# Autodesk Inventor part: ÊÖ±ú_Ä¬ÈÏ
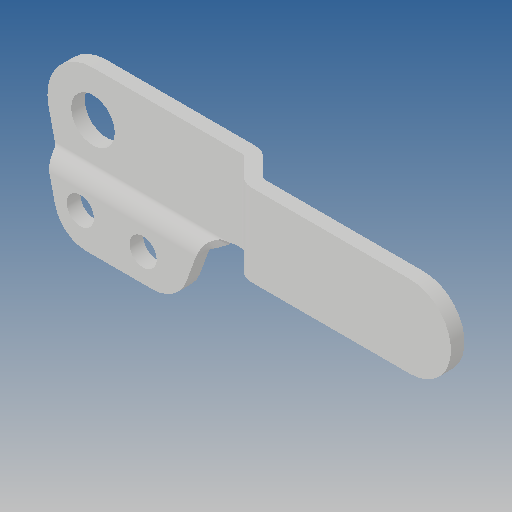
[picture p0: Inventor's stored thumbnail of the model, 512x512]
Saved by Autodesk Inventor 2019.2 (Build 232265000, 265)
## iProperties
Created: 2012-09
Part Number: ÊÖ±ú_Ä¬ÈÏ
Material: Ogólny
Document SubType Name: Modeling
Designer: CADENGINEERING4
Density: 1 g/cm^3
Appearance: Domyślna
Author: CADENGINEERING4
Revision Number: ÈÎºÎ
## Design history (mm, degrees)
feature "NONE"
node "Bryła1"
